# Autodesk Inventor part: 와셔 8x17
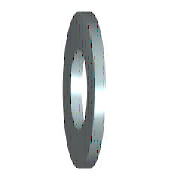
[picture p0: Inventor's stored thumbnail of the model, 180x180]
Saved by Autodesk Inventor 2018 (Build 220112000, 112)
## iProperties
IsCustomPart: 1
Created: 2012-02
Part Number: 와셔 8x17
Material: 강철, 연강
Description: 평면 와셔
Document SubType Name: Modeling
Standard: KS B 1326
Designer: mduedu
Standards Organization: KS
Language: ko-KR
Size Designation: 8x17
Categories: <MemberInstance><Categories><Category DisplayName="조임쇠" InternalName="e4da775c-781d-43d5-af7c-5136215cf5a6" Mnemonic="FSTN"><Category DisplayName="와셔" InternalN
Density: 1 g/cm^3
Appearance: 노란색
Author: mduedu
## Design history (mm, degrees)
sketch "스케치"
  geometry: C1 r 8.5 at (0, 0); C2 r 4.2 at (0, 0); 1 further point
  constraints: 2 centre point, 2 coincident
  dimensions: "d0" = 8.4 diameter of C2 (= SD1); "d1" = 17 diameter of C1 (= SD2)
extrude "본체" new body sketch "스케치" distance "d2" = 1.6 (= SD); taper "d3" = 0 deg
workaxis "Work Axis1"
workplane "Work Plane1"
body "Solid1"
other parameters: "SD1" = 8.4 [user parameter; used in 1 equation term], "SD2" = 17 [user parameter; used in 1 equation term], "SD" = 1.6 [user parameter; used in 1 equation term], "d4" = 0, "d5" = 0, "d6" = 0, "d7" = 0, "NND" = 8 [user parameter]
